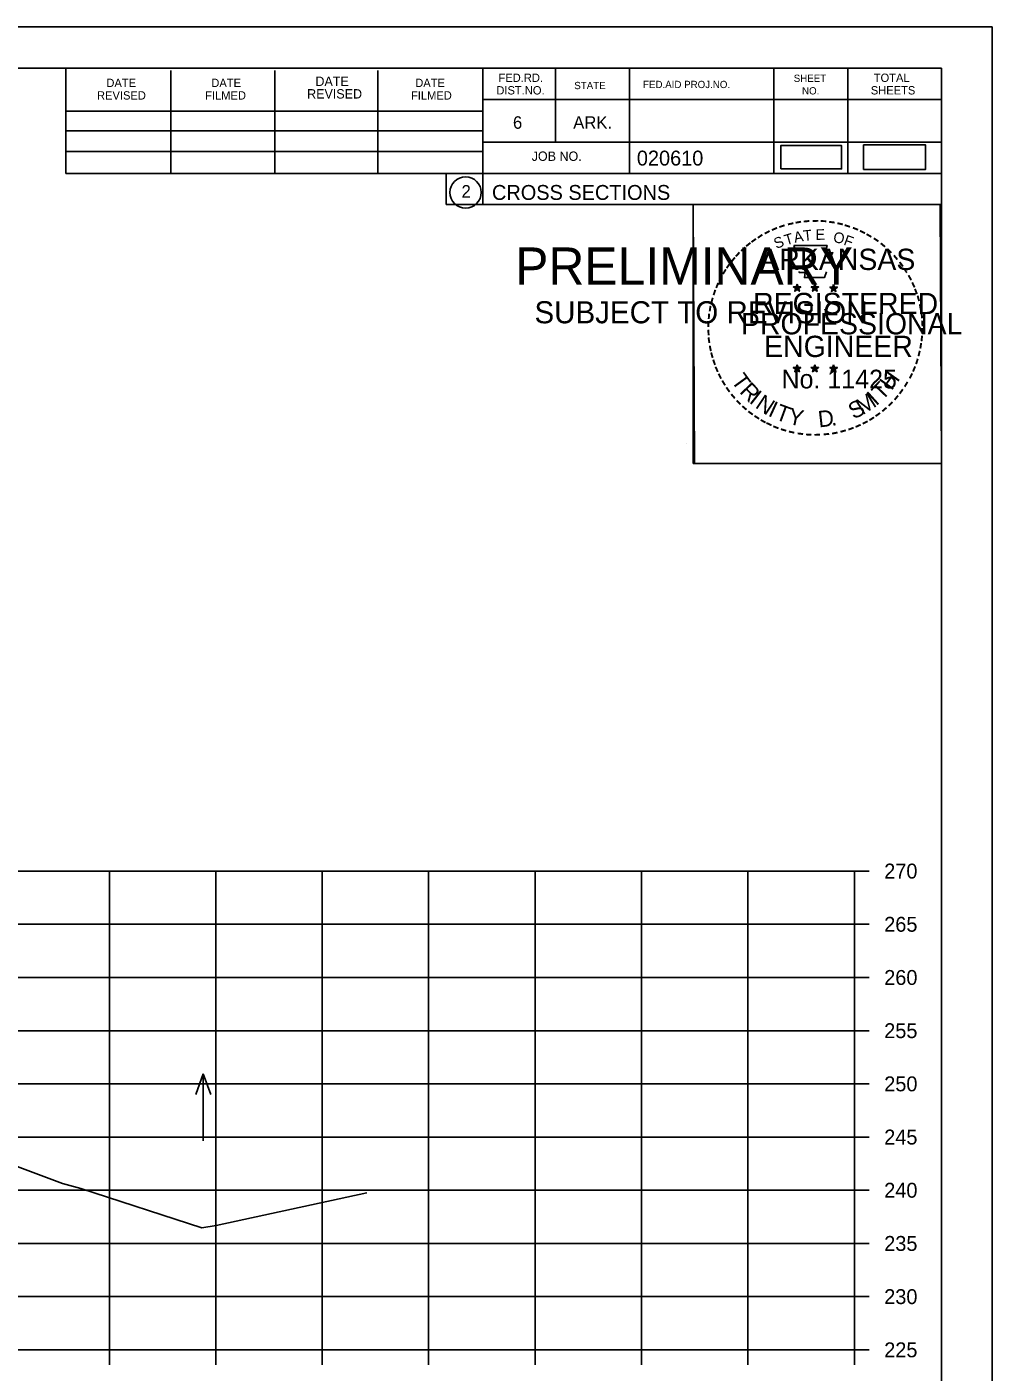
# Model space of a CAD drawing. Extents: x 1103485 to 1107180, y 2010593 to 2011873.
# Drawn here: x 1107089.4 to 1107180.1, y 2011746.4 to 2011872.9 of the extents above; entities that cross this region are included whole.
import ezdxf

# ---------------------------------------------------------------- set-up
doc = ezdxf.new("R2010")
doc.units = 0
for name, color, linetype in [('R_Axis', 7, 'Continuous'), ('R_Axis Annot', 7, 'Continuous'), ('R_Border', 7, 'Continuous'), ('R_Border PE', 7, 'Continuous'), ('R_Border Prem', 7, 'Continuous'), ('R_Exist Surface', 7, 'Continuous'), ('R_Grid', 7, 'Continuous'), ('R_No Plot', 7, 'Continuous'), ('R_Water', 7, 'Continuous'), ('R_Water Annot', 7, 'Continuous')]:
    doc.layers.add(name, color=color, linetype=linetype)

msp = doc.modelspace()

# ---------------------------------------------------------------- linework, layer by layer
at = {"layer": 'R_Axis'}
for p, q in [((1107167.18, 2011748.51), (1107167.18, 2011793.51)), ((1107168.58, 2011793.51), (1107167.18, 2011793.51)), ((1107168.58, 2011788.51), (1107167.18, 2011788.51)), ((1107168.58, 2011783.51), (1107167.18, 2011783.51)), ((1107168.58, 2011778.51), (1107167.18, 2011778.51)), ((1107168.58, 2011773.51), (1107167.18, 2011773.51)), ((1107168.58, 2011768.51), (1107167.18, 2011768.51)), ((1107168.58, 2011763.51), (1107167.18, 2011763.51)), ((1107168.58, 2011758.51), (1107167.18, 2011758.51)), ((1107168.58, 2011753.51), (1107167.18, 2011753.51)), ((1106867.18, 2011748.51), (1107167.18, 2011748.51)), ((1107097.18, 2011747.11), (1107097.18, 2011748.51)), ((1107107.18, 2011747.11), (1107107.18, 2011748.51)), ((1107117.18, 2011747.11), (1107117.18, 2011748.51)), ((1107127.18, 2011747.11), (1107127.18, 2011748.51)), ((1107137.18, 2011747.11), (1107137.18, 2011748.51)), ((1107147.18, 2011747.11), (1107147.18, 2011748.51)), ((1107157.18, 2011747.11), (1107157.18, 2011748.51)), ((1107167.18, 2011747.11), (1107167.18, 2011748.51)), ((1107168.58, 2011748.51), (1107167.18, 2011748.51))]:
    msp.add_line(p, q, dxfattribs=at)
at = {"layer": 'R_Border'}
for p, q in [((1106859.18, 2011868.97), (1107175.36, 2011868.97)), ((1107093.1, 2011859.09), (1107093.1, 2011868.97)), ((1107102.96, 2011859.09), (1107102.96, 2011868.77)), ((1107112.72, 2011859.09), (1107112.72, 2011868.77)), ((1107122.4, 2011859.09), (1107122.4, 2011868.77)), ((1107132.26, 2011868.97), (1107132.26, 2011856.17)), ((1107139.1, 2011868.97), (1107139.1, 2011862.03)), ((1107146.04, 2011868.97), (1107146.04, 2011859.09)), ((1107159.62, 2011868.97), (1107159.62, 2011859.09)), ((1107166.56, 2011868.97), (1107166.56, 2011859.09)), ((1107175.36, 2011663.51), (1107175.36, 2011868.97)), ((1107175.36, 2011866.03), (1107132.26, 2011866.03)), ((1107175.36, 2011866.05), (1107175.36, 2011866.05)), ((1107093.1, 2011864.95), (1107132.26, 2011864.95)), ((1107093.1, 2011863.09), (1107132.26, 2011863.09)), ((1107175.36, 2011862.03), (1107132.26, 2011862.03)), ((1107135.22, 2011862.03), (1107175.36, 2011862.03)), ((1107093.1, 2011859.09), (1107093.1, 2011861.15)), ((1107093.1, 2011861.15), (1107132.26, 2011861.15)), ((1107175.36, 2011859.09), (1107093.1, 2011859.09)), ((1107132.26, 2011856.17), (1107175.36, 2011856.17))]:
    msp.add_line(p, q, dxfattribs=at)
msp.add_circle((1107130.65, 2011857.3), 1.47, dxfattribs=at)
at = {"layer": 'R_Border PE'}
for p, q in [((1107161.45, 2011848.42), (1107161.8, 2011848.31)), ((1107161.45, 2011848.42), (1107161.7, 2011848.38)), ((1107161.45, 2011848.42), (1107161.69, 2011848.3)), ((1107161.58, 2011848.01), (1107161.8, 2011848.31)), ((1107161.58, 2011848.01), (1107161.71, 2011848.26)), ((1107161.58, 2011848.01), (1107161.8, 2011848.23)), ((1107161.8, 2011848.68), (1107161.76, 2011848.42)), ((1107161.8, 2011848.31), (1107161.8, 2011848.68)), ((1107161.8, 2011848.68), (1107161.85, 2011848.43)), ((1107162.14, 2011848.42), (1107161.8, 2011848.31)), ((1107162.01, 2011848.01), (1107161.8, 2011848.31)), ((1107162.01, 2011848.01), (1107161.8, 2011848.23)), ((1107162.14, 2011848.42), (1107161.86, 2011848.37)), ((1107162.01, 2011848.01), (1107161.87, 2011848.3)), ((1107162.14, 2011848.42), (1107161.94, 2011848.32)), ((1107163.12, 2011848.42), (1107163.47, 2011848.31)), ((1107163.12, 2011848.42), (1107163.37, 2011848.38)), ((1107163.12, 2011848.42), (1107163.36, 2011848.3)), ((1107163.25, 2011848.01), (1107163.47, 2011848.31)), ((1107163.25, 2011848.01), (1107163.38, 2011848.26)), ((1107163.25, 2011848.01), (1107163.47, 2011848.23)), ((1107163.47, 2011848.68), (1107163.43, 2011848.42)), ((1107163.47, 2011848.31), (1107163.47, 2011848.68)), ((1107163.47, 2011848.68), (1107163.52, 2011848.43)), ((1107163.81, 2011848.42), (1107163.47, 2011848.31)), ((1107163.68, 2011848.01), (1107163.47, 2011848.31)), ((1107163.68, 2011848.01), (1107163.47, 2011848.23)), ((1107163.81, 2011848.42), (1107163.53, 2011848.37)), ((1107163.68, 2011848.01), (1107163.54, 2011848.3)), ((1107163.81, 2011848.42), (1107163.61, 2011848.32)), ((1107164.88, 2011848.41), (1107165.23, 2011848.3)), ((1107164.88, 2011848.41), (1107165.14, 2011848.36)), ((1107164.88, 2011848.41), (1107165.12, 2011848.29)), ((1107165.02, 2011848), (1107165.23, 2011848.3)), ((1107165.02, 2011848), (1107165.14, 2011848.25)), ((1107165.02, 2011848), (1107165.23, 2011848.22)), ((1107165.23, 2011848.66), (1107165.19, 2011848.41)), ((1107165.23, 2011848.3), (1107165.23, 2011848.66)), ((1107165.23, 2011848.66), (1107165.28, 2011848.41)), ((1107165.58, 2011848.41), (1107165.23, 2011848.3)), ((1107165.44, 2011848), (1107165.23, 2011848.3)), ((1107165.44, 2011848), (1107165.23, 2011848.22)), ((1107165.58, 2011848.41), (1107165.29, 2011848.36)), ((1107165.44, 2011848), (1107165.31, 2011848.29)), ((1107165.58, 2011848.41), (1107165.37, 2011848.31)), ((1107161.44, 2011840.85), (1107161.79, 2011840.74)), ((1107161.44, 2011840.85), (1107161.7, 2011840.8)), ((1107161.44, 2011840.85), (1107161.68, 2011840.73)), ((1107161.58, 2011840.44), (1107161.79, 2011840.74)), ((1107161.58, 2011840.44), (1107161.7, 2011840.68)), ((1107161.58, 2011840.44), (1107161.79, 2011840.66)), ((1107161.79, 2011841.1), (1107161.75, 2011840.85)), ((1107161.79, 2011840.74), (1107161.79, 2011841.1)), ((1107161.79, 2011841.1), (1107161.84, 2011840.85)), ((1107162.14, 2011840.85), (1107161.79, 2011840.74)), ((1107162.01, 2011840.44), (1107161.79, 2011840.74)), ((1107162.01, 2011840.44), (1107161.79, 2011840.65)), ((1107162.14, 2011840.85), (1107161.85, 2011840.8)), ((1107162.01, 2011840.44), (1107161.87, 2011840.73)), ((1107162.14, 2011840.85), (1107161.94, 2011840.75)), ((1107163.11, 2011840.85), (1107163.46, 2011840.74)), ((1107163.11, 2011840.85), (1107163.37, 2011840.8)), ((1107163.11, 2011840.85), (1107163.35, 2011840.73)), ((1107163.25, 2011840.44), (1107163.46, 2011840.74)), ((1107163.25, 2011840.44), (1107163.37, 2011840.68)), ((1107163.25, 2011840.44), (1107163.46, 2011840.66)), ((1107163.46, 2011841.1), (1107163.42, 2011840.85)), ((1107163.46, 2011840.74), (1107163.46, 2011841.1)), ((1107163.46, 2011841.1), (1107163.51, 2011840.85)), ((1107163.81, 2011840.85), (1107163.46, 2011840.74)), ((1107163.68, 2011840.44), (1107163.46, 2011840.74)), ((1107163.68, 2011840.44), (1107163.46, 2011840.65)), ((1107163.81, 2011840.85), (1107163.52, 2011840.8)), ((1107163.68, 2011840.44), (1107163.54, 2011840.73)), ((1107163.81, 2011840.85), (1107163.61, 2011840.75)), ((1107164.88, 2011840.84), (1107165.23, 2011840.73)), ((1107164.88, 2011840.84), (1107165.13, 2011840.79)), ((1107164.88, 2011840.84), (1107165.12, 2011840.72)), ((1107165.01, 2011840.43), (1107165.23, 2011840.73)), ((1107165.01, 2011840.43), (1107165.14, 2011840.67)), ((1107165.01, 2011840.43), (1107165.23, 2011840.65)), ((1107165.23, 2011841.09), (1107165.19, 2011840.84)), ((1107165.23, 2011840.73), (1107165.23, 2011841.09)), ((1107165.23, 2011841.09), (1107165.28, 2011840.84)), ((1107165.58, 2011840.84), (1107165.23, 2011840.73)), ((1107165.44, 2011840.43), (1107165.23, 2011840.73)), ((1107165.44, 2011840.43), (1107165.23, 2011840.64)), ((1107165.58, 2011840.84), (1107165.29, 2011840.79)), ((1107165.44, 2011840.43), (1107165.31, 2011840.72)), ((1107165.58, 2011840.84), (1107165.37, 2011840.74))]:
    msp.add_line(p, q, dxfattribs=at)
for points in [[(1107161.49, 2011852.3), (1107161.76, 2011851.47)], [(1107165, 2011851.38), (1107165.14, 2011851.66), (1107164.46, 2011851.64), (1107164.61, 2011852.3), (1107161.49, 2011852.3)], [(1107161.98, 2011849.88), (1107161.98, 2011849.79), (1107162.54, 2011849.77), (1107162.49, 2011849.3), (1107164.36, 2011849.3), (1107164.56, 2011849.83)], [(1107161.8, 2011848.68), (1107162.01, 2011848.01), (1107161.45, 2011848.42), (1107162.14, 2011848.42), (1107161.58, 2011848.01), (1107161.8, 2011848.68)], [(1107163.47, 2011848.68), (1107163.68, 2011848.01), (1107163.12, 2011848.42), (1107163.81, 2011848.42), (1107163.25, 2011848.01), (1107163.47, 2011848.68)], [(1107165.23, 2011848.66), (1107165.44, 2011848), (1107164.88, 2011848.41), (1107165.58, 2011848.41), (1107165.02, 2011848), (1107165.23, 2011848.66)], [(1107161.79, 2011841.1), (1107162.01, 2011840.44), (1107161.44, 2011840.85), (1107162.14, 2011840.85), (1107161.58, 2011840.44), (1107161.79, 2011841.1)], [(1107163.46, 2011841.1), (1107163.68, 2011840.44), (1107163.11, 2011840.85), (1107163.81, 2011840.85), (1107163.25, 2011840.44), (1107163.46, 2011841.1)], [(1107165.23, 2011841.09), (1107165.44, 2011840.43), (1107164.88, 2011840.84), (1107165.58, 2011840.84), (1107165.01, 2011840.43), (1107165.23, 2011841.09)]]:
    msp.add_lwpolyline(points, dxfattribs=at)
for centre, radius in [((1107161.8, 2011848.31), 0.172), ((1107161.8, 2011848.31), 0.145), ((1107161.8, 2011848.31), 0.116), ((1107161.8, 2011848.31), 0.0991), ((1107161.8, 2011848.31), 0.0747), ((1107161.8, 2011848.31), 0.0495), ((1107161.8, 2011848.31), 0.0296), ((1107163.47, 2011848.31), 0.172), ((1107163.47, 2011848.31), 0.145), ((1107163.47, 2011848.31), 0.116), ((1107163.47, 2011848.31), 0.0991), ((1107163.47, 2011848.31), 0.0747), ((1107163.47, 2011848.31), 0.0495), ((1107163.47, 2011848.31), 0.0296), ((1107165.23, 2011848.3), 0.172), ((1107165.23, 2011848.3), 0.145), ((1107165.23, 2011848.3), 0.116), ((1107165.23, 2011848.3), 0.0991), ((1107165.23, 2011848.3), 0.0747), ((1107165.23, 2011848.3), 0.0495), ((1107165.23, 2011848.3), 0.0296), ((1107161.79, 2011840.74), 0.172), ((1107161.79, 2011840.74), 0.145), ((1107161.79, 2011840.74), 0.116), ((1107161.79, 2011840.74), 0.0991), ((1107161.79, 2011840.74), 0.0747), ((1107161.79, 2011840.74), 0.0495), ((1107161.79, 2011840.74), 0.0296), ((1107163.46, 2011840.74), 0.172), ((1107163.46, 2011840.74), 0.145), ((1107163.46, 2011840.74), 0.116), ((1107163.46, 2011840.74), 0.0991), ((1107163.46, 2011840.74), 0.0747), ((1107163.46, 2011840.74), 0.0495), ((1107163.46, 2011840.74), 0.0296), ((1107165.23, 2011840.73), 0.172), ((1107165.23, 2011840.73), 0.145), ((1107165.23, 2011840.73), 0.116), ((1107165.23, 2011840.73), 0.0991), ((1107165.23, 2011840.73), 0.0747), ((1107165.23, 2011840.73), 0.0495), ((1107165.23, 2011840.73), 0.0296)]:
    msp.add_circle(centre, radius, dxfattribs=at)
at = {"layer": 'R_Exist Surface'}
msp.add_lwpolyline([(1106998.64, 2011782.16), (1107001.63, 2011782.17), (1107004.98, 2011782.18), (1107017.87, 2011782.24), (1107021.63, 2011782.18), (1107024.75, 2011782.12), (1107030.5, 2011781.94), (1107034.7, 2011781.77), (1107044.78, 2011779.65), (1107062.07, 2011776.22), (1107082.97, 2011767.89), (1107085.3, 2011766.95), (1107088.27, 2011765.84), (1107092.79, 2011764.16), (1107094.49, 2011763.68), (1107105.87, 2011759.98), (1107107.21, 2011760.21), (1107121.37, 2011763.28)], dxfattribs=at)
at = {"layer": 'R_Grid'}
for p, q in [((1106867.18, 2011793.51), (1107167.18, 2011793.51)), ((1107097.18, 2011748.51), (1107097.18, 2011793.51)), ((1107107.18, 2011748.51), (1107107.18, 2011793.51)), ((1107117.18, 2011748.51), (1107117.18, 2011793.51)), ((1107127.18, 2011748.51), (1107127.18, 2011793.51)), ((1107137.18, 2011748.51), (1107137.18, 2011793.51)), ((1107147.18, 2011748.51), (1107147.18, 2011793.51)), ((1107157.18, 2011748.51), (1107157.18, 2011793.51)), ((1107167.18, 2011748.51), (1107167.18, 2011793.51)), ((1106867.18, 2011788.51), (1107167.18, 2011788.51)), ((1106867.18, 2011783.51), (1107167.18, 2011783.51)), ((1106867.18, 2011778.51), (1107167.18, 2011778.51)), ((1106867.18, 2011773.51), (1107167.18, 2011773.51)), ((1106867.18, 2011768.51), (1107167.18, 2011768.51)), ((1106867.18, 2011763.51), (1107167.18, 2011763.51)), ((1106867.18, 2011758.51), (1107167.18, 2011758.51)), ((1106867.18, 2011753.51), (1107167.18, 2011753.51)), ((1106867.18, 2011748.51), (1107167.18, 2011748.51))]:
    msp.add_line(p, q, dxfattribs=at)
at = {"layer": 'R_No Plot'}
for p, q in [((1106846.78, 2011872.86), (1107180.12, 2011872.86)), ((1107151.4, 2011833.71), (1107151.4, 2011833.71))]:
    msp.add_line(p, q, dxfattribs=at)
for points in [[(1106846.78, 2011872.86), (1107180.12, 2011872.86), (1107180.12, 2011659.52), (1106846.78, 2011659.52)], [(1107093.1, 2011868.97), (1107093.1, 2011859.09), (1107128.84, 2011859.09), (1107128.84, 2011856.17), (1107152.04, 2011856.17), (1107152.04, 2011831.83), (1107175.36, 2011831.83), (1107175.36, 2011663.51), (1106859.18, 2011663.51), (1106859.18, 2011868.97)], [(1107152.04, 2011856.17), (1107175.24, 2011856.17), (1107175.36, 2011831.83), (1107152.16, 2011831.83)]]:
    msp.add_lwpolyline(points, close=True, dxfattribs=at)
at = {"layer": 'R_Water'}
for points in [[(1107160.26, 2011859.52), (1107165.97, 2011859.52), (1107165.97, 2011861.71), (1107160.26, 2011861.71)], [(1107168.04, 2011859.46), (1107173.87, 2011859.46), (1107173.87, 2011861.77), (1107168.04, 2011861.77)]]:
    msp.add_lwpolyline(points, close=True, dxfattribs=at)
at = {"layer": 'R_Water Annot'}
for p, q in [((1107106, 2011774.44), (1107105.3, 2011772.51)), ((1107106, 2011768.15), (1107106, 2011774.44)), ((1107106, 2011774.44), (1107106.7, 2011772.51))]:
    msp.add_line(p, q, dxfattribs=at)

# ---------------------------------------------------------------- texts
at = {"layer": 'R_Axis Annot'}
for s, p in [('270', (1107169.98, 2011792.81)), ('265', (1107169.98, 2011787.81)), ('260', (1107169.98, 2011782.81)), ('255', (1107169.98, 2011777.81)), ('250', (1107169.98, 2011772.81)), ('245', (1107169.98, 2011767.81)), ('240', (1107169.98, 2011762.81)), ('235', (1107169.98, 2011757.81)), ('230', (1107169.98, 2011752.81)), ('225', (1107169.98, 2011747.81))]:
    msp.add_text(s, height=1.4, dxfattribs=at).set_placement(p)
at = {"layer": 'R_Border'}
for s, height, p in [('DATE', 0.879, (1107116.54, 2011867.31)), ('FED.RD.', 0.782, (1107133.74, 2011867.69)), ('SHEET', 0.684, (1107161.48, 2011867.69)), ('TOTAL', 0.782, (1107169, 2011867.69)), ('REVISED', 0.782, (1107096.02, 2011866.03)), ('DATE', 0.782, (1107096.9, 2011867.21)), ('FILMED', 0.782, (1107106.18, 2011866.03)), ('DATE', 0.782, (1107106.76, 2011867.21)), ('REVISED', 0.879, (1107115.76, 2011866.13)), ('FILMED', 0.782, (1107125.52, 2011866.03)), ('DATE', 0.782, (1107125.92, 2011867.21)), ('DIST.NO.', 0.782, (1107133.54, 2011866.51)), ('STATE', 0.684, (1107140.86, 2011867.01)), ('FED.AID PROJ.NO.', 0.684, (1107147.32, 2011867.11)), ('NO.', 0.684, (1107162.26, 2011866.51)), ('SHEETS', 0.782, (1107168.72, 2011866.51)), ('6', 1.17, (1107135.1, 2011863.29)), ('ARK.', 1.172, (1107140.76, 2011863.29)), ('JOB NO.', 0.879, (1107136.86, 2011860.27)), ('020610', 1.4, (1107146.74, 2011859.83)), ('2', 1.17, (1107130.27, 2011856.82)), ('CROSS SECTIONS', 1.4, (1107133.13, 2011856.6))]:
    msp.add_text(s, height=height, rotation=360, dxfattribs=at).set_placement(p)
at = {"layer": 'R_Border PE'}
for s, height, rotation, p in [('-', 1.6, 19.1761, (1107160.24, 2011853.43)), ('-', 1.6, 13.6301, (1107160.99, 2011853.67)), ('-', 1.6, 10.2193, (1107161.67, 2011853.83)), ('-', 1.6, 5.8968, (1107162.39, 2011853.94)), ('-', 1.6, 0.1862, (1107163.17, 2011854.01)), ('-', 1.6, 357.743, (1107163.89, 2011854)), ('-', 1.6, 352.1617, (1107164.63, 2011853.94)), ('-', 1.6, 347.2049, (1107165.35, 2011853.83)), ('-', 1.6, 342.3362, (1107165.99, 2011853.67)), ('-', 1.6, 36.2317, (1107157.8, 2011852.08)), ('-', 1.6, 34.0636, (1107158.37, 2011852.47)), ('-', 1.6, 28.7918, (1107158.97, 2011852.84)), ('-', 1.6, 24.3072, (1107159.6, 2011853.16)), ('S', 1, 21.594, (1107159.84, 2011851.98)), ('T', 1, 16.4036, (1107160.76, 2011852.31)), ('A', 1, 11.2132, (1107161.58, 2011852.56)), ('T', 1, 6.0228, (1107162.43, 2011852.73)), ('E', 1, 0.8323, (1107163.54, 2011852.84)), ('O', 1, 350.4515, (1107165.14, 2011852.63)), ('F', 1, 340.0707, (1107166.1, 2011852.4)), ('-', 1.6, 337.8551, (1107166.72, 2011853.45)), ('-', 1.6, 334.1211, (1107167.35, 2011853.18)), ('-', 1.6, 329.6409, (1107167.93, 2011852.9)), ('-', 1.6, 325.8627, (1107168.58, 2011852.54)), ('-', 1.6, 48.423, (1107156.44, 2011850.8)), ('-', 1.6, 42.9622, (1107156.89, 2011851.28)), ('-', 1.6, 38.9507, (1107157.32, 2011851.7)), ('ARKANSAS', 2, 360, (1107158.34, 2011850.01)), ('-', 1.6, 320.5297, (1107169.19, 2011852.11)), ('-', 1.6, 315.5786, (1107169.78, 2011851.62)), ('-', 1.6, 54.2325, (1107155.62, 2011849.75)), ('-', 1.6, 50.6142, (1107156.04, 2011850.32)), ('-', 1.6, 309.8797, (1107170.35, 2011851.07)), ('-', 1.6, 306.6522, (1107170.88, 2011850.47)), ('-', 1.6, 62.8713, (1107154.98, 2011848.61)), ('-', 1.6, 58.0706, (1107155.3, 2011849.22)), ('-', 1.4, 303.6753, (1107171.36, 2011849.9)), ('-', 1.6, 299.6684, (1107171.68, 2011849.29)), ('-', 1.6, 72.3945, (1107154.51, 2011847.37)), ('-', 1.6, 67.7743, (1107154.73, 2011848)), ('REGISTERED', 2, 360, (1107157.66, 2011845.86)), ('DWB', 0.01, 360, (1107161.78, 2011848.31)), ('DWB', 0.01, 360, (1107163.45, 2011848.31)), ('DWB', 0.01, 360, (1107165.22, 2011848.29)), ('-', 1.6, 294.6628, (1107172.01, 2011848.68)), ('-', 1.6, 290.5728, (1107172.26, 2011848.11)), ('-', 1.6, 81.2013, (1107154.18, 2011845.94)), ('-', 1.6, 75.461, (1107154.31, 2011846.65)), ('-', 1.6, 285.1233, (1107172.5, 2011847.53)), ('-', 1.6, 280.5493, (1107172.7, 2011846.78)), ('-', 1.6, 85.1863, (1107154.1, 2011845.25)), ('PROFESSIONAL', 2, 360, (1107156.52, 2011843.96)), ('-', 1.6, 276.5962, (1107172.86, 2011846.02)), ('-', 1.6, 274.3301, (1107172.92, 2011845.29)), ('-', 1.6, 94.1959, (1107154.11, 2011843.82)), ('-', 1.6, 89.0622, (1107154.08, 2011844.55)), ('-', 1.6, 269.9407, (1107172.95, 2011844.66)), ('-', 1.6, 98.9479, (1107154.18, 2011843.16)), ('-', 1.6, 101.7149, (1107154.32, 2011842.42)), ('ENGINEER', 2, 360, (1107158.7, 2011841.83)), ('-', 1.6, 260.9953, (1107172.86, 2011843.34)), ('-', 1.6, 263.5172, (1107172.94, 2011844)), ('-', 1.6, 105.4578, (1107154.48, 2011841.83)), ('-', 1.6, 109.0874, (1107154.7, 2011841.2)), ('-', 1.6, 252.8681, (1107172.57, 2011841.94)), ('-', 1.6, 255.7626, (1107172.75, 2011842.66)), ('-', 1.6, 114.0643, (1107154.95, 2011840.6)), ('-', 1.6, 115.7289, (1107155.25, 2011839.98)), ('T', 1.54, 306.0406, (1107155.55, 2011839.58)), ('No. 11425', 1.757, 360, (1107160.33, 2011838.88)), ('DWB', 0.01, 360, (1107161.78, 2011840.73)), ('DWB', 0.01, 360, (1107163.45, 2011840.73)), ('DWB', 0.01, 360, (1107165.22, 2011840.72)), ('H', 1.54, 54.6088, (1107170.67, 2011838.61)), ('-', 1.6, 244.6197, (1107172.09, 2011840.64)), ('-', 1.6, 247.8887, (1107172.35, 2011841.27)), ('-', 1.6, 120.4471, (1107155.61, 2011839.4)), ('-', 1.6, 125.8934, (1107156.01, 2011838.84)), ('R', 1.54, 314.005, (1107156.32, 2011838.53)), ('T', 1.54, 46.6444, (1107169.78, 2011837.67)), ('-', 1.6, 239.0712, (1107171.69, 2011839.89)), ('-', 1.6, 130.7181, (1107156.48, 2011838.28)), ('-', 1.6, 134.2238, (1107156.99, 2011837.74)), ('I', 1.54, 321.9694, (1107157.22, 2011837.6)), ('N', 1.54, 326.5002, (1107157.78, 2011837.12)), ('I', 1.54, 335.3603, (1107158.99, 2011836.34)), ('S', 1.54, 26.9312, (1107167.1, 2011835.94)), ('M', 1.54, 32.6563, (1107167.94, 2011836.34)), ('I', 1.54, 42.1136, (1107169.22, 2011837.19)), ('-', 1.6, 225.7653, (1107170.38, 2011838.11)), ('-', 1.6, 231.2538, (1107170.86, 2011838.67)), ('-', 1.6, 233.8452, (1107171.29, 2011839.24)), ('-', 1.6, 138.9338, (1107157.52, 2011837.28)), ('-', 1.6, 144.6463, (1107158.07, 2011836.87)), ('T', 1.54, 339.8912, (1107159.65, 2011836.01)), ('Y', 1.54, 347.8556, (1107160.87, 2011835.57)), ('D', 1.54, 6.3969, (1107163.85, 2011835.21)), ('-', 1.6, 215.7363, (1107169.31, 2011837.13)), ('-', 1.6, 221.0851, (1107169.86, 2011837.6)), ('-', 1.6, 148.0898, (1107158.64, 2011836.5)), ('-', 1.6, 151.5704, (1107159.21, 2011836.17)), ('-', 1.6, 154.6002, (1107159.74, 2011835.93)), ('-', 1.6, 158.5612, (1107160.36, 2011835.67)), ('-', 1.6, 162.7983, (1107161.05, 2011835.46)), ('.', 1.54, 13.7642, (1107165.05, 2011835.33)), ('-', 1.6, 200.7184, (1107166.98, 2011835.8)), ('-', 1.6, 204.2516, (1107167.6, 2011836.07)), ('-', 1.6, 207.3568, (1107168.22, 2011836.39)), ('-', 1.6, 212.2491, (1107168.78, 2011836.74)), ('-', 1.6, 167.5555, (1107161.76, 2011835.3)), ('-', 1.6, 173.1155, (1107162.53, 2011835.19)), ('-', 1.6, 176.5183, (1107163.28, 2011835.13)), ('-', 1.6, 181.5918, (1107164.03, 2011835.15)), ('-', 1.6, 185.8167, (1107164.84, 2011835.23)), ('-', 1.6, 191.2858, (1107165.57, 2011835.36)), ('-', 1.6, 195.4743, (1107166.3, 2011835.56))]:
    msp.add_text(s, height=height, rotation=rotation, dxfattribs=at).set_placement(p)
at = {"layer": 'R_Border Prem'}
for s, height, p in [('PRELIMINARY', 3.5, (1107135.31, 2011848.63)), ('DWB', 0.01, (1107136.06, 2011850.48)), ('SUBJECT TO REVISION', 2.0751, (1107137.12, 2011845))]:
    msp.add_text(s, height=height, rotation=360, dxfattribs=at).set_placement(p)

doc.saveas('drawing.dxf')
